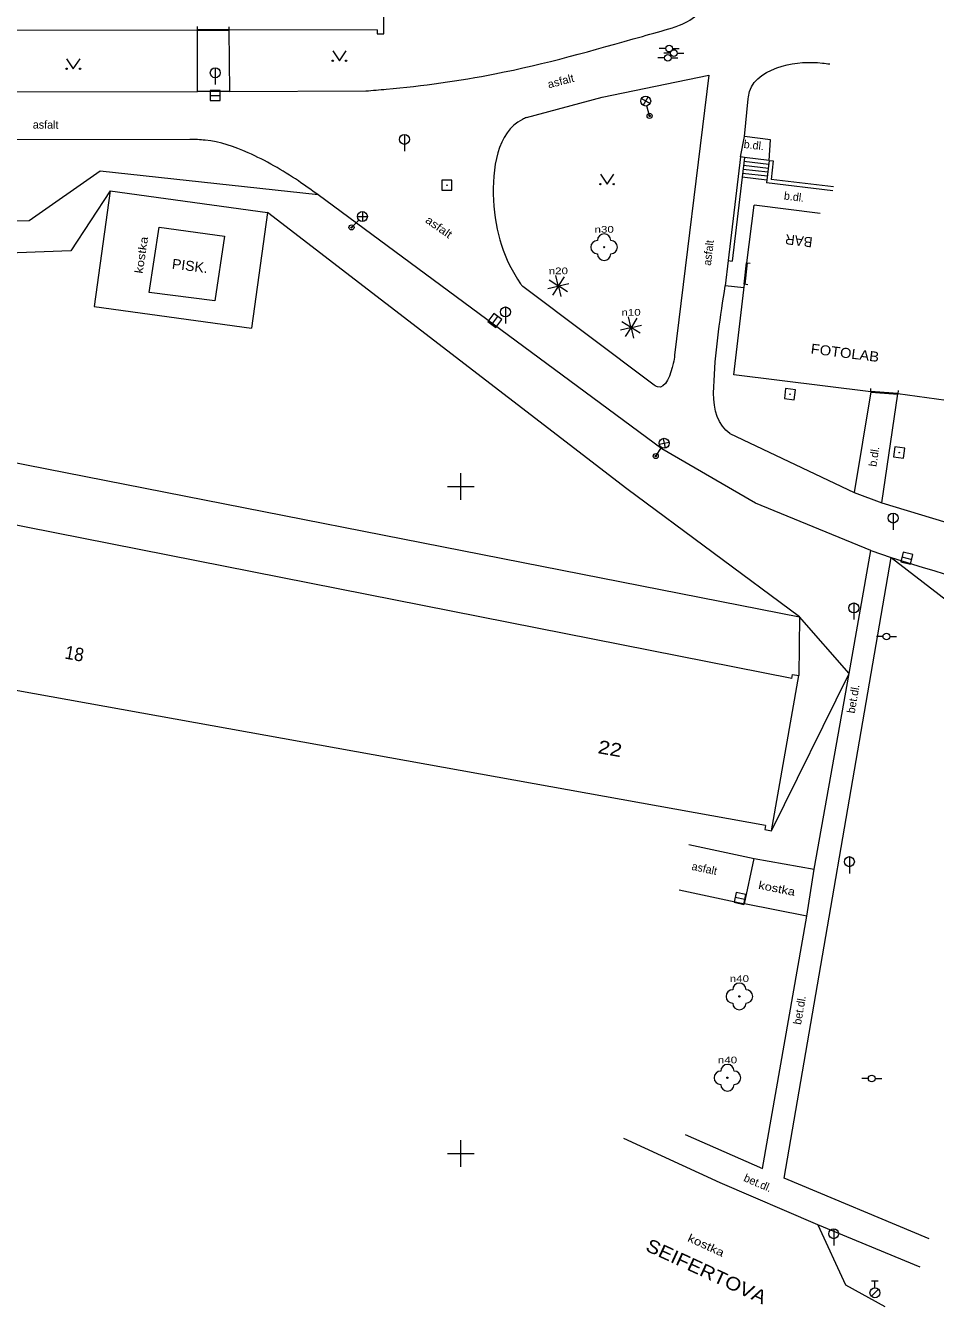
# Model space of a CAD drawing. Extents: x -670514 to -669423, y -1130798 to -1130123.
# Drawn here: x -670382.6 to -670314.4, y -1130561.5 to -1130465.5 of the extents above; entities that cross this region are included whole.
import ezdxf
from ezdxf.enums import TextEntityAlignment as Align

# ---------------------------------------------------------------- set-up
doc = ezdxf.new("R2010")
doc.units = 0
doc.header["$LTSCALE"] = 0.24
for name, color, linetype, lineweight in [('10', 7, 'Continuous', 13), ('11', 7, 'Continuous', 13), ('14', 7, 'Continuous', 13), ('22', 7, 'Continuous', 13), ('26', 7, 'Continuous', 13), ('27', 7, 'Continuous', 13), ('28', 7, 'Continuous', 13), ('33', 7, 'Continuous', 13), ('36', 7, 'Continuous', 13), ('45', 7, 'Continuous', 13), ('5', 7, 'Continuous', 13), ('6', 7, 'Continuous', 13), ('61', 7, 'Continuous', 13), ('7', 7, 'Continuous', 13)]:
    doc.layers.add(name, color=color, linetype=linetype, lineweight=lineweight)
for name, color, linetype in [('40', 7, 'Continuous'), ('41', 7, 'Continuous'), ('42', 7, 'Continuous'), ('44', 7, 'Continuous')]:
    doc.layers.add(name, color=color, linetype=linetype)

msp = doc.modelspace()

# ---------------------------------------------------------------- linework, layer by layer
at = {"layer": '10'}
for p, q in [((-670331.425, -1130469.191), (-670333.978, -1130490.157)), ((-670370.322, -1130474.001), (-670418.162, -1130474.105)), ((-670326.951, -1130476.168), (-670328.815, -1130475.946)), ((-670326.916, -1130475.87), (-670328.78, -1130475.648)), ((-670326.881, -1130475.573), (-670328.745, -1130475.351)), ((-670327.058, -1130477.062), (-670328.922, -1130476.84)), ((-670327.022, -1130476.764), (-670328.886, -1130476.542)), ((-670326.987, -1130476.466), (-670328.851, -1130476.244)), ((-670376.288, -1130477.847), (-670377.476, -1130486.52)), ((-670335.601, -1130492.343), (-670345.364, -1130485.031)), ((-670328.779, -1130485.125), (-670330.181, -1130484.961)), ((-670377.476, -1130486.52), (-670365.682, -1130488.146)), ((-670319.279, -1130492.921), (-670320.523, -1130500.457)), ((-670318.459, -1130501.241), (-670317.236, -1130493.057)), ((-670319.276, -1130504.815), (-670317.755, -1130505.337)), ((-670332.906, -1130526.842), (-670328.018, -1130527.895)), ((-670333.636, -1130530.232), (-670328.748, -1130531.285)), ((-670330.556, -1130552.194), (-670337.793, -1130548.865)), ((-670323.237, -1130555.341), (-670330.556, -1130552.194)), ((-670315.566, -1130558.523), (-670323.237, -1130555.341))]:
    msp.add_line(p, q, dxfattribs=at)
for points in [[(-670388.979, -1130465.827), (-670388.977, -1130470.429), (-670369.741, -1130470.406), (-670369.731, -1130465.796)], [(-670367.378, -1130465.81), (-670367.349, -1130470.417), (-670357.121, -1130470.365)], [(-670345.083, -1130472.359), (-670339.405, -1130470.845), (-670331.425, -1130469.191)], [(-670329.043, -1130475.316), (-670328.744, -1130473.79), (-670328.458, -1130470.96)], [(-670326.881, -1130475.573), (-670326.799, -1130474.042), (-670328.744, -1130473.79)], [(-670376.288, -1130477.847), (-670364.494, -1130479.473), (-670365.682, -1130488.146)], [(-670319.276, -1130504.815), (-670327.916, -1130501.257), (-670334.942, -1130497.196), (-670360.693, -1130478.162)], [(-670329.851, -1130496.047), (-670320.523, -1130500.457), (-670318.459, -1130501.241), (-670309.783, -1130503.852)], [(-670333.183, -1130548.579), (-670327.398, -1130551.12), (-670324.067, -1130532.223), (-670323.517, -1130528.701), (-670320.9, -1130514.03), (-670319.276, -1130504.815)], [(-670314.907, -1130556.389), (-670325.774, -1130551.848), (-670317.755, -1130505.337)], [(-670324.067, -1130532.223), (-670328.748, -1130531.285), (-670328.018, -1130527.895), (-670323.517, -1130528.701)], [(-670323.237, -1130555.341), (-670321.162, -1130559.843), (-670318.225, -1130561.457)]]:
    msp.add_lwpolyline(points, dxfattribs=at)
msp.add_lwpolyline([(-670367.713, -1130481.258), (-670368.428, -1130486.099), (-670373.355, -1130485.479), (-670372.609, -1130480.573)], close=True, dxfattribs=at)
for points in [[(-670334.132, -1130465.635), (-670333.602, -1130465.44), (-670332.155, -1130464.536), (-670330.929, -1130461.857), (-670330.845, -1130461.332)], [(-670357.121, -1130470.365), (-670355.587, -1130470.235), (-670347.44, -1130469.088), (-670336.39, -1130466.274), (-670334.132, -1130465.635)], [(-670328.458, -1130470.96), (-670328.357, -1130470.4), (-670325.926, -1130468.513), (-670322.895, -1130468.278), (-670322.352, -1130468.341)], [(-670345.083, -1130472.359), (-670345.383, -1130472.498), (-670347.552, -1130478.559), (-670345.518, -1130484.814), (-670345.364, -1130485.031)], [(-670360.693, -1130478.162), (-670362.174, -1130477.115), (-670365.94, -1130474.999), (-670369.157, -1130474.058), (-670370.322, -1130474.001)], [(-670329.851, -1130496.047), (-670330.392, -1130495.5), (-670331.025, -1130492.086), (-670330.181, -1130484.961)], [(-670333.978, -1130490.157), (-670334.08, -1130490.794), (-670335.255, -1130492.55), (-670335.601, -1130492.343)], [(-670317.755, -1130505.337), (-670292.115, -1130512.843), (-670276.449, -1130516.697)]]:
    msp.add_spline(points, degree=3, dxfattribs=at)
at = {"layer": '11'}
for p, q in [((-670367.349, -1130470.417), (-670369.741, -1130470.406)), ((-670329.969, -1130483.084), (-670330.181, -1130484.961))]:
    msp.add_line(p, q, dxfattribs=at)
at = {"layer": '14'}
for points in [[(-670360.693, -1130478.162), (-670377.039, -1130476.373), (-670382.363, -1130480.113), (-670413.708, -1130480.415)], [(-670376.288, -1130477.847), (-670379.229, -1130482.342), (-670413.849, -1130483.645)], [(-670324.629, -1130509.773), (-670337.557, -1130500.196), (-670364.494, -1130479.473)], [(-670387.512, -1130514.853), (-670394.529, -1130496.029), (-670324.629, -1130509.773)], [(-670317.755, -1130505.337), (-670310.559, -1130510.868), (-670276.449, -1130516.697)], [(-670326.722, -1130525.805), (-670320.9, -1130514.03), (-670324.629, -1130509.773), (-670324.657, -1130514.187)]]:
    msp.add_lwpolyline(points, dxfattribs=at)
at = {"layer": '22'}
for p, q in [((-670342.724, -1130484.966), (-670343.38, -1130484.552)), ((-670342.698, -1130484.946), (-670342.87, -1130484.192)), ((-670342.256, -1130484.296), (-670342.67, -1130484.952)), ((-670342.65, -1130484.978), (-670341.896, -1130484.806)), ((-670343.484, -1130485.166), (-670342.73, -1130484.994)), ((-670342.71, -1130485.02), (-670343.124, -1130485.676)), ((-670342.682, -1130485.026), (-670342.51, -1130485.78)), ((-670342, -1130485.42), (-670342.656, -1130485.006)), ((-670337.275, -1130488.072), (-670337.931, -1130487.658)), ((-670337.249, -1130488.052), (-670337.421, -1130487.298)), ((-670336.807, -1130487.402), (-670337.221, -1130488.058)), ((-670338.035, -1130488.272), (-670337.281, -1130488.1)), ((-670337.261, -1130488.126), (-670337.675, -1130488.782)), ((-670337.233, -1130488.132), (-670337.061, -1130488.886)), ((-670336.551, -1130488.526), (-670337.207, -1130488.112)), ((-670337.201, -1130488.084), (-670336.447, -1130487.912))]:
    msp.add_line(p, q, dxfattribs=at)
for centre, radius in [((-670339.259, -1130482.075), 0.05), ((-670342.69, -1130484.986), 0.04), ((-670337.241, -1130488.092), 0.04), ((-670329.124, -1130538.228), 0.05), ((-670330.017, -1130544.324), 0.05)]:
    msp.add_circle(centre, radius, dxfattribs=at)
for centre, start, end in [((-670339.759, -1130482.075), 90, 270), ((-670339.259, -1130481.575), 0, 180), ((-670338.759, -1130482.075), 270, 90), ((-670339.259, -1130482.575), 180, 0), ((-670329.124, -1130537.728), 0, 180), ((-670329.624, -1130538.228), 90, 270), ((-670328.624, -1130538.228), 270, 90), ((-670329.124, -1130538.728), 180, 0), ((-670330.017, -1130543.824), 0, 180), ((-670330.517, -1130544.324), 90, 270), ((-670329.517, -1130544.324), 270, 90), ((-670330.017, -1130544.824), 180, 0)]:
    msp.add_arc(centre, 0.5, start, end, dxfattribs=at)
at = {"layer": '26'}
for points in [[(-670350.664, -1130477.81), (-670350.664, -1130477.06), (-670351.414, -1130477.06), (-670351.414, -1130477.81)], [(-670325.753, -1130493.419), (-670325.009, -1130493.515), (-670324.913, -1130492.771), (-670325.657, -1130492.675)], [(-670317.567, -1130497.785), (-670316.824, -1130497.888), (-670316.721, -1130497.145), (-670317.464, -1130497.042)]]:
    msp.add_lwpolyline(points, close=True, dxfattribs=at)
for centre in [(-670351.039, -1130477.4349), (-670325.3329, -1130493.095), (-670317.1439, -1130497.465)]:
    msp.add_circle(centre, 0.02, dxfattribs=at)
at = {"layer": '27'}
for p, q in [((-670368.403, -1130468.63), (-670368.403, -1130469.88)), ((-670368.792, -1130470.704), (-670368.042, -1130470.704)), ((-670354.227, -1130473.62), (-670354.227, -1130474.87)), ((-670346.655, -1130486.557), (-670346.655, -1130487.807)), ((-670347.674, -1130487.862), (-670347.22, -1130487.266)), ((-670317.606, -1130501.998), (-670317.606, -1130503.248)), ((-670316.937, -1130505.289), (-670316.211, -1130505.473)), ((-670320.547, -1130508.74), (-670320.547, -1130509.99)), ((-670320.882, -1130527.753), (-670320.882, -1130529.003)), ((-670328.711, -1130530.959), (-670329.445, -1130530.801)), ((-670322.057, -1130555.633), (-670322.057, -1130556.883))]:
    msp.add_line(p, q, dxfattribs=at)
for points in [[(-670368.792, -1130471.078), (-670368.042, -1130471.078), (-670368.042, -1130470.328), (-670368.792, -1130470.328)], [(-670347.377, -1130488.089), (-670346.922, -1130487.492), (-670347.519, -1130487.038), (-670347.973, -1130487.635)], [(-670317.03, -1130505.651), (-670316.303, -1130505.836), (-670316.118, -1130505.109), (-670316.845, -1130504.924)], [(-670328.633, -1130530.593), (-670329.366, -1130530.435), (-670329.524, -1130531.169), (-670328.791, -1130531.327)]]:
    msp.add_lwpolyline(points, close=True, dxfattribs=at)
for centre in [(-670368.4026, -1130469.0051), (-670354.2266, -1130473.9951), (-670346.6546, -1130486.9321), (-670317.6056, -1130502.3731), (-670320.5466, -1130509.1151), (-670320.8816, -1130528.1281), (-670322.0566, -1130556.0081)]:
    msp.add_circle(centre, 0.375, dxfattribs=at)
at = {"layer": '28'}
for p, q in [((-670334.631, -1130467.195), (-670335.131, -1130467.195)), ((-670334.291, -1130467.527), (-670334.791, -1130467.527)), ((-670334.131, -1130467.195), (-670333.631, -1130467.195)), ((-670333.791, -1130467.527), (-670333.291, -1130467.527)), ((-670334.731, -1130467.886), (-670335.231, -1130467.886)), ((-670334.231, -1130467.886), (-670333.731, -1130467.886)), ((-670318.355, -1130511.249), (-670318.855, -1130511.249)), ((-670317.855, -1130511.249), (-670317.355, -1130511.249)), ((-670319.458, -1130544.38), (-670319.958, -1130544.38)), ((-670318.958, -1130544.38), (-670318.458, -1130544.38)), ((-670319.211, -1130559.535), (-670318.711, -1130559.535)), ((-670318.961, -1130560.06), (-670318.961, -1130559.535)), ((-670319.226, -1130560.7), (-670318.696, -1130560.17))]:
    msp.add_line(p, q, dxfattribs=at)
for centre, radius in [((-670334.3812, -1130467.1953), 0.25), ((-670334.0413, -1130467.5273), 0.25), ((-670334.4813, -1130467.8862), 0.25), ((-670318.1053, -1130511.2493), 0.25), ((-670319.2083, -1130544.3802), 0.25), ((-670318.961, -1130560.435), 0.375)]:
    msp.add_circle(centre, radius, dxfattribs=at)
at = {"layer": '33'}
for p, q in [((-670336.467, -1130470.934), (-670335.82, -1130471.313)), ((-670336.332, -1130471.447), (-670335.954, -1130470.8)), ((-670335.852, -1130472.236), (-670336.048, -1130471.486)), ((-670357.753, -1130479.784), (-670357.003, -1130479.784)), ((-670357.377, -1130479.409), (-670357.378, -1130480.158)), ((-670358.192, -1130480.596), (-670357.643, -1130480.049)), ((-670335.393, -1130497.733), (-670334.966, -1130497.086)), ((-670335.127, -1130496.848), (-670334.393, -1130496.698)), ((-670334.835, -1130496.406), (-670334.684, -1130497.14))]:
    msp.add_line(p, q, dxfattribs=at)
for centre, radius in [((-670336.1432, -1130471.1235), 0.375), ((-670335.852, -1130472.236), 0.19), ((-670335.852, -1130472.236), 0.05), ((-670357.3778, -1130479.7839), 0.375), ((-670358.192, -1130480.596), 0.19), ((-670358.192, -1130480.596), 0.05), ((-670334.7597, -1130496.7731), 0.375), ((-670335.393, -1130497.733), 0.19), ((-670335.393, -1130497.733), 0.05)]:
    msp.add_circle(centre, radius, dxfattribs=at)
at = {"layer": '36'}
for points in [[(-670359.597, -1130467.355), (-670359.097, -1130468.105), (-670358.597, -1130467.355)], [(-670379.541, -1130467.953), (-670379.041, -1130468.703), (-670378.541, -1130467.953)], [(-670339.544, -1130476.604), (-670339.044, -1130477.354), (-670338.544, -1130476.604)]]:
    msp.add_lwpolyline(points, dxfattribs=at)
for centre in [(-670359.597, -1130468.105), (-670358.597, -1130468.105), (-670379.541, -1130468.703), (-670378.541, -1130468.703), (-670339.544, -1130477.354), (-670338.544, -1130477.354)]:
    msp.add_circle(centre, 0.05, dxfattribs=at)
at = {"layer": '5'}
for p, q in [((-670355.758, -1130466.086), (-670355.75, -1130454.289)), ((-670388.979, -1130465.827), (-670369.731, -1130465.796)), ((-670356.258, -1130465.786), (-670367.378, -1130465.81)), ((-670356.258, -1130465.786), (-670356.258, -1130466.086)), ((-670356.258, -1130466.086), (-670355.758, -1130466.086)), ((-670328.555, -1130483.241), (-670328.023, -1130478.932)), ((-670323.061, -1130479.545), (-670328.023, -1130478.932)), ((-670329.539, -1130491.631), (-670328.748, -1130484.858)), ((-670319.279, -1130492.921), (-670329.539, -1130491.631)), ((-670325.201, -1130514.395), (-670384.852, -1130502.614)), ((-670326.722, -1130525.805), (-670324.657, -1130514.187)), ((-670325.201, -1130514.395), (-670325.149, -1130514.1)), ((-670325.149, -1130514.1), (-670324.657, -1130514.187)), ((-670327.162, -1130525.423), (-670386.968, -1130514.645)), ((-670327.162, -1130525.423), (-670327.214, -1130525.718)), ((-670327.214, -1130525.718), (-670326.722, -1130525.805))]:
    msp.add_line(p, q, dxfattribs=at)
msp.add_lwpolyline([(-670305.102, -1130499.552), (-670310.63, -1130498.838), (-670310.01, -1130494.063), (-670317.236, -1130493.057)], dxfattribs=at)
at = {"layer": '6'}
for p, q in [((-670369.731, -1130465.796), (-670369.729, -1130465.546)), ((-670367.376, -1130465.56), (-670367.378, -1130465.81)), ((-670328.555, -1130483.241), (-670328.306, -1130483.27)), ((-670328.499, -1130484.887), (-670328.748, -1130484.858)), ((-670319.279, -1130492.921), (-670319.262, -1130492.671)), ((-670317.219, -1130492.807), (-670317.236, -1130493.057))]:
    msp.add_line(p, q, dxfattribs=at)
at = {"layer": '6', "lineweight": 35}
for p, q in [((-670369.731, -1130465.796), (-670367.378, -1130465.81)), ((-670328.555, -1130483.241), (-670328.748, -1130484.858)), ((-670319.279, -1130492.921), (-670317.236, -1130493.057))]:
    msp.add_line(p, q, dxfattribs=at)
at = {"layer": '61'}
for p, q in [((-670350, -1130501), (-670350, -1130499)), ((-670351, -1130500), (-670349, -1130500)), ((-670350, -1130551), (-670350, -1130549)), ((-670351, -1130550), (-670349, -1130550))]:
    msp.add_line(p, q, dxfattribs=at)
at = {"layer": '7'}
for p, q in [((-670329.043, -1130475.316), (-670329.969, -1130483.084)), ((-670328.745, -1130475.351), (-670329.671, -1130483.119)), ((-670328.745, -1130475.351), (-670329.043, -1130475.316)), ((-670326.881, -1130475.573), (-670327.082, -1130477.262)), ((-670326.881, -1130475.573), (-670326.583, -1130475.608)), ((-670326.583, -1130475.608), (-670326.749, -1130476.999)), ((-670322.081, -1130477.555), (-670326.749, -1130476.999)), ((-670322.117, -1130477.853), (-670327.082, -1130477.262)), ((-670329.969, -1130483.084), (-670329.671, -1130483.119))]:
    msp.add_line(p, q, dxfattribs=at)

# ---------------------------------------------------------------- texts
at = {"layer": '22', "width": 1.3}
for s, p in [('n30', (-670339.2585, -1130480.989)), ('n20', (-670342.6905, -1130484.1)), ('n10', (-670337.2415, -1130487.206)), ('n40', (-670329.1235, -1130537.142)), ('n40', (-670330.0165, -1130543.238))]:
    msp.add_text(s, height=0.499, dxfattribs=at).set_placement(p, align=Align.CENTER)
at = {"layer": '40'}
for s, rotation, width, p in [('asfalt', 14.93, 1.05, (-670342.4343, -1130469.9212)), ('asfalt', 324.741, 1.15, (-670351.8152, -1130480.8108)), ('kostka', 81.354, 1.2, (-670373.6411, -1130482.7056)), ('kostka', 348.669, 1.2, (-670326.3729, -1130530.4272)), ('kostka', 335.298, 1.25, (-670331.7414, -1130557.1468))]:
    msp.add_text(s, height=0.6, rotation=rotation, dxfattribs=dict(at, width=width)).set_placement(p, align=Align.CENTER)
for s, rotation, p in [('asfalt', 359.433, (-670381.12, -1130473.1939)), ('b.dl.', 353.208, (-670328.073, -1130474.7262)), ('b.dl.', 352.957, (-670325.0583, -1130478.5921)), ('asfalt', 83.202, (-670331.1472, -1130482.5325)), ('b.dl.', 81.501, (-670318.7439, -1130497.8053)), ('bet.dl.', 80.218, (-670320.2989, -1130515.9715)), ('asfalt', 347.843, (-670331.8052, -1130528.9353)), ('bet.dl.', 80.218, (-670324.3209, -1130539.3025)), ('bet.dl.', 336.733, (-670327.8535, -1130552.4761))]:
    msp.add_text(s, height=0.6, rotation=rotation, dxfattribs=at).set_placement(p, align=Align.CENTER)
at = {"layer": '41'}
msp.add_text('BAR', height=0.75, rotation=172.957, dxfattribs=at).set_placement((-670324.6265, -1130481.2259), align=Align.CENTER)
at = {"layer": '42'}
for s, rotation, width, p in [('PISK.', 352.828, 1.05, (-670370.3483, -1130483.8489)), ('FOTOLAB', 352.834, 1.1, (-670321.2538, -1130490.3642))]:
    msp.add_text(s, height=0.75, rotation=rotation, dxfattribs=dict(at, width=width)).set_placement(p, align=Align.CENTER)
at = {"layer": '44'}
for s, rotation, width, p in [('18', 349.784, 0.95, (-670379.0422, -1130513.0249)), ('22', 350.002, 1.2, (-670338.8983, -1130520.1468))]:
    msp.add_text(s, height=1, rotation=rotation, dxfattribs=dict(at, width=width)).set_placement(p, align=Align.CENTER)
at = {"layer": '45', "width": 1.15}
msp.add_text('SEIFERTOVA', height=1, rotation=335.298, dxfattribs=at).set_placement((-670331.8065, -1130559.283), align=Align.CENTER)

doc.saveas('drawing.dxf')
